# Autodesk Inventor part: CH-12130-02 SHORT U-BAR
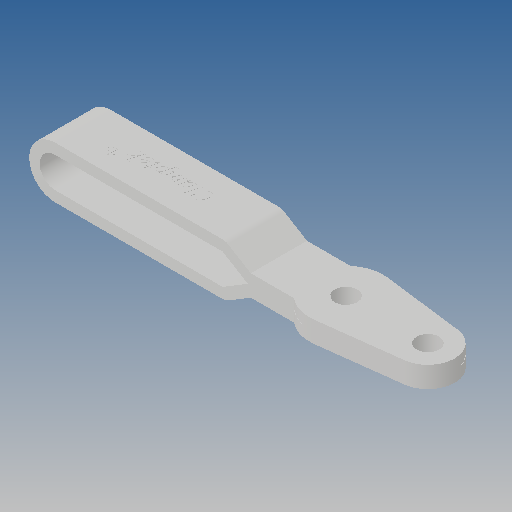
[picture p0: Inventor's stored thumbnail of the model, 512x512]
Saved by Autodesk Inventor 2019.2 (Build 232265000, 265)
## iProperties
Created: 2012-09
Part Number: CH-12130-02 SHORT U-BAR
Material: Ogólny
Document SubType Name: Modeling
Designer: CADENGINEERING4
Density: 1 g/cm^3
Appearance: Domyślna
Author: CADENGINEERING4
Revision Number: ÈÎºÎ
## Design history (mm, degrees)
feature "ÇÐ³ý-À­Éì2"
feature "ÇÐ³ý-À­Éì6"
node "Bryła1"
node "Bryła2"
